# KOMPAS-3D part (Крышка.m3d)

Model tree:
1. Эскиз:1
2. Операция выдавливания:1
     Расстояние 1 = 4; Расстояние 2 = 125
3. Эскиз:2
4. Операция выдавливания:2
     Расстояние 1 = 4.5; Расстояние 2 = 125
5. Фаска:1
     Угол = 45; Длина 1 = 2; Длина 2 = 2
6. Фаска:2
     Угол = 45; Длина 1 = 1; Длина 2 = 1
